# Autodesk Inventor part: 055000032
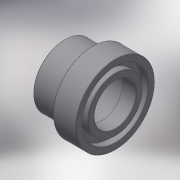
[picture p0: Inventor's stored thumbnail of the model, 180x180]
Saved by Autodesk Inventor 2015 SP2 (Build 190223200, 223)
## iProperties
Created: 2017-10
Part Number: 055000032
Material: Generic
Description: PLASSON FLANGE AD.+O-RING-CE 32
Document SubType Name: Modeling
Designer: KIM
Density: 1 g/cm^3
Appearance: Default
Author: KIM
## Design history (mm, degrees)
derived "055000.ipt"
feature "Solid1::055000.ipt"
tag "TaggingFeature1"
body "Solid1"
other parameters: "d0" = 28, "d1" = 41, "d2" = 32, "d3" = 28.8, "d5" = 22, "d8" = 3, "d11" = 0.32, "d12" = 3, "d15" = 3.18, "d_" = 32, "E_" = 41, "l_" = 22, "H_" = 28, "d14" = 10.6
